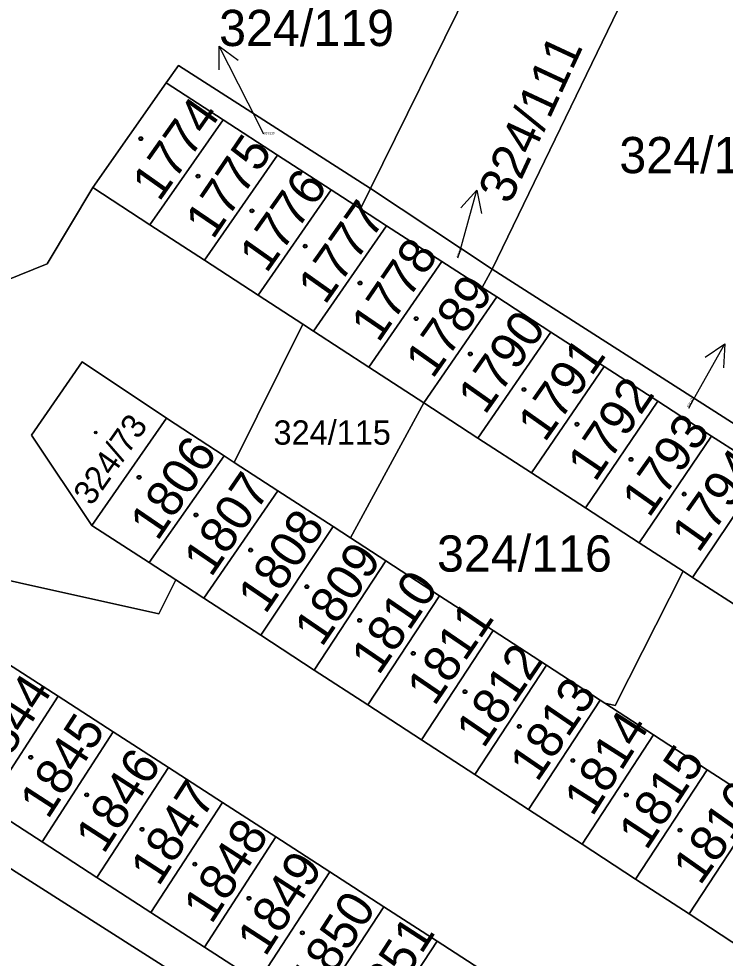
# Model space of a CAD drawing. Extents: x -598233 to -596890, y -1157848 to -1156431.
# Drawn here: x -597215.44 to -597182.25, y -1157620.12 to -1157576.01 of the extents above; entities that cross this region are included whole.
import ezdxf

# ---------------------------------------------------------------- set-up
doc = ezdxf.new("R2010")
doc.units = 0
for name, color, linetype in [('Level 1', 7, 'Continuous'), ('Level 4', 7, 'Continuous'), ('Level 5', 7, 'Continuous'), ('Level 57', 7, 'Continuous'), ('Level 60', 7, 'Continuous')]:
    doc.layers.add(name, color=color, linetype=linetype)

msp = doc.modelspace()

# ---------------------------------------------------------------- linework, layer by layer
at = {"layer": 'Level 1'}
for points in [[(-597198.92, -1157583.98), (-597189.61, -1157565.11)], [(-597193.21, -1157587.77), (-597184.82, -1157570.47)], [(-597208.52, -1157579.02), (-597207.94, -1157578.2), (-597198.92, -1157583.98)], [(-597211.97, -1157583.94), (-597208.52, -1157579.02)], [(-597208.52, -1157579.02), (-597205.84, -1157580.76)], [(-597205.84, -1157580.76), (-597209.28, -1157585.69)], [(-597205.84, -1157580.76), (-597203.28, -1157582.41)], [(-597206.72, -1157587.35), (-597203.28, -1157582.41)], [(-597203.28, -1157582.41), (-597200.77, -1157584.04)], [(-597228.65, -1157599.56), (-597223.33, -1157591.25), (-597214.11, -1157587.51), (-597211.97, -1157583.94)], [(-597209.28, -1157585.69), (-597211.97, -1157583.94)], [(-597198.92, -1157583.98), (-597199.39, -1157584.93)], [(-597198.92, -1157583.98), (-597193.21, -1157587.77)], [(-597204.2, -1157588.99), (-597200.77, -1157584.04)], [(-597200.77, -1157584.04), (-597199.39, -1157584.93)], [(-597199.39, -1157584.93), (-597198.16, -1157585.73)], [(-597209.28, -1157585.69), (-597206.72, -1157587.35)], [(-597198.16, -1157585.73), (-597201.59, -1157590.68)], [(-597198.16, -1157585.73), (-597195.57, -1157587.41)], [(-597204.2, -1157588.99), (-597206.72, -1157587.35)], [(-597198.99, -1157592.37), (-597195.57, -1157587.41)], [(-597195.57, -1157587.41), (-597193.67, -1157588.63)], [(-597193.21, -1157587.77), (-597193.67, -1157588.63)], [(-597193.21, -1157587.77), (-597181, -1157595.57)], [(-597193.67, -1157588.63), (-597192.99, -1157589.07)], [(-597202.09, -1157590.35), (-597204.2, -1157588.99)], [(-597192.99, -1157589.07), (-597196.41, -1157594.04)], [(-597192.99, -1157589.07), (-597190.45, -1157590.72)], [(-597202.09, -1157590.35), (-597205.32, -1157596.84)], [(-597201.59, -1157590.68), (-597202.09, -1157590.35)], [(-597201.59, -1157590.68), (-597198.99, -1157592.37)], [(-597193.87, -1157595.7), (-597190.45, -1157590.72)], [(-597190.45, -1157590.72), (-597187.94, -1157592.34)], [(-597212.01, -1157599.8), (-597214.85, -1157595.57), (-597212.47, -1157592.12), (-597208.51, -1157594.76)], [(-597198.99, -1157592.37), (-597196.41, -1157594.04)], [(-597187.94, -1157592.34), (-597191.35, -1157597.33)], [(-597187.94, -1157592.34), (-597185.42, -1157593.97)], [(-597199.86, -1157600.38), (-597196.41, -1157594.04)], [(-597196.41, -1157594.04), (-597193.87, -1157595.7)], [(-597185.42, -1157593.97), (-597188.82, -1157598.97)], [(-597185.42, -1157593.97), (-597182.89, -1157595.61)], [(-597208.51, -1157594.76), (-597212.01, -1157599.8)], [(-597205.79, -1157596.53), (-597208.51, -1157594.76)], [(-597191.35, -1157597.33), (-597193.87, -1157595.7)], [(-597186.29, -1157600.62), (-597182.89, -1157595.61)], [(-597182.89, -1157595.61), (-597181.48, -1157596.52)], [(-597205.79, -1157596.53), (-597209.31, -1157601.55)], [(-597205.32, -1157596.84), (-597205.79, -1157596.53)], [(-597203.27, -1157598.17), (-597205.32, -1157596.84)], [(-597180.4, -1157597.22), (-597183.79, -1157602.24)], [(-597191.35, -1157597.33), (-597188.82, -1157598.97)], [(-597206.75, -1157603.22), (-597203.27, -1157598.17)], [(-597200.68, -1157599.85), (-597203.27, -1157598.17)], [(-597188.82, -1157598.97), (-597186.29, -1157600.62)], [(-597144.73, -1157635.19), (-597124.59, -1157647.92), (-597112.62, -1157653.99), (-597115.75, -1157660.25), (-597114.28, -1157671.45), (-597118.54, -1157677.88), (-597228.54, -1157607.83), (-597232.29, -1157605.23), (-597228.65, -1157599.56)], [(-597208.07, -1157602.36), (-597208.87, -1157603.96), (-597228.65, -1157599.56)], [(-597212.01, -1157599.8), (-597209.31, -1157601.55)], [(-597200.68, -1157599.85), (-597204.07, -1157604.96)], [(-597199.86, -1157600.38), (-597200.68, -1157599.85)], [(-597198.2, -1157601.46), (-597199.86, -1157600.38)], [(-597184.23, -1157601.95), (-597186.29, -1157600.62)], [(-597209.31, -1157601.55), (-597208.07, -1157602.36)], [(-597201.56, -1157606.6), (-597198.2, -1157601.46)], [(-597195.67, -1157603.11), (-597198.2, -1157601.46)], [(-597187.91, -1157608.15), (-597187.42, -1157608.25), (-597184.23, -1157601.95)], [(-597183.79, -1157602.24), (-597184.23, -1157601.95)], [(-597208.07, -1157602.36), (-597206.75, -1157603.22)], [(-597183.79, -1157602.24), (-597181.21, -1157603.91)], [(-597206.75, -1157603.22), (-597204.07, -1157604.96)], [(-597195.67, -1157603.11), (-597199.04, -1157608.23)], [(-597193.15, -1157604.74), (-597195.67, -1157603.11)], [(-597193.15, -1157604.74), (-597196.53, -1157609.87)], [(-597190.65, -1157606.37), (-597193.15, -1157604.74)], [(-597204.07, -1157604.96), (-597201.56, -1157606.6)], [(-597216.19, -1157606.14), (-597213.59, -1157607.82)], [(-597194.01, -1157611.5), (-597190.65, -1157606.37)], [(-597188.13, -1157608.01), (-597190.65, -1157606.37)], [(-597201.56, -1157606.6), (-597199.04, -1157608.23)], [(-597213.59, -1157607.82), (-597216.94, -1157612.98)], [(-597213.59, -1157607.82), (-597211.01, -1157609.49)], [(-597199.04, -1157608.23), (-597196.53, -1157609.87)], [(-597188.13, -1157608.01), (-597191.5, -1157613.14)], [(-597187.91, -1157608.15), (-597188.13, -1157608.01)], [(-597185.62, -1157609.64), (-597187.91, -1157608.15)], [(-597214.35, -1157614.66), (-597211.01, -1157609.49)], [(-597211.01, -1157609.49), (-597208.41, -1157611.17)], [(-597196.53, -1157609.87), (-597194.01, -1157611.5)], [(-597185.62, -1157609.64), (-597188.98, -1157614.77)], [(-597183.1, -1157611.28), (-597185.62, -1157609.64)], [(-597211.78, -1157616.33), (-597208.41, -1157611.17)], [(-597208.41, -1157611.17), (-597205.87, -1157612.81)], [(-597186.47, -1157616.41), (-597183.1, -1157611.28)], [(-597180.58, -1157612.91), (-597183.1, -1157611.28)], [(-597194.01, -1157611.5), (-597191.5, -1157613.14)], [(-597214.35, -1157614.66), (-597216.94, -1157612.98)], [(-597205.87, -1157612.81), (-597209.24, -1157617.98)], [(-597205.87, -1157612.81), (-597203.36, -1157614.43)], [(-597183.95, -1157618.04), (-597180.58, -1157612.91)], [(-597191.5, -1157613.14), (-597188.98, -1157614.77)], [(-597206.72, -1157619.61), (-597203.36, -1157614.43)], [(-597203.36, -1157614.43), (-597200.83, -1157616.07)], [(-597211.78, -1157616.33), (-597214.35, -1157614.66)], [(-597188.98, -1157614.77), (-597186.47, -1157616.41)], [(-597200.83, -1157616.07), (-597204.2, -1157621.24)], [(-597200.83, -1157616.07), (-597198.29, -1157617.71)], [(-597209.24, -1157617.98), (-597211.78, -1157616.33)], [(-597186.47, -1157616.41), (-597183.95, -1157618.04)], [(-597206.72, -1157619.61), (-597209.24, -1157617.98)], [(-597198.29, -1157617.71), (-597201.67, -1157622.88)], [(-597198.29, -1157617.71), (-597195.79, -1157619.33)], [(-597183.95, -1157618.04), (-597181.44, -1157619.68)], [(-597204.2, -1157621.24), (-597206.72, -1157619.61)], [(-597195.79, -1157619.33), (-597199.18, -1157624.5)], [(-597195.79, -1157619.33), (-597193.21, -1157621)]]:
    msp.add_lwpolyline(points, dxfattribs=at)
at = {"layer": 'Level 5'}
for centre, radius in [((-597209.71, -1157581.64), 0.09), ((-597209.71, -1157581.64), 0.0521), ((-597207.02, -1157583.4), 0.09), ((-597207.02, -1157583.4), 0.0521), ((-597204.49, -1157585.03), 0.09), ((-597204.49, -1157585.03), 0.0521), ((-597201.99, -1157586.69), 0.09), ((-597201.99, -1157586.69), 0.0521), ((-597199.41, -1157588.42), 0.09), ((-597199.41, -1157588.42), 0.0521), ((-597196.77, -1157590.09), 0.09), ((-597196.77, -1157590.09), 0.0521), ((-597194.23, -1157591.75), 0.09), ((-597194.23, -1157591.75), 0.0521), ((-597191.71, -1157593.42), 0.09), ((-597191.71, -1157593.42), 0.0521), ((-597189.22, -1157595.05), 0.09), ((-597189.22, -1157595.05), 0.0521), ((-597211.83, -1157595.44), 0.0612), ((-597211.83, -1157595.44), 0.0354), ((-597186.68, -1157596.7), 0.09), ((-597186.68, -1157596.7), 0.0521), ((-597209.79, -1157597.54), 0.09), ((-597209.79, -1157597.54), 0.0521), ((-597184.18, -1157598.33), 0.09), ((-597184.18, -1157598.33), 0.0521), ((-597207.12, -1157599.31), 0.09), ((-597207.12, -1157599.31), 0.0521), ((-597204.55, -1157600.96), 0.09), ((-597204.55, -1157600.96), 0.0521), ((-597201.91, -1157602.68), 0.09), ((-597201.91, -1157602.68), 0.0521), ((-597199.43, -1157604.26), 0.09), ((-597199.43, -1157604.26), 0.0521), ((-597196.91, -1157605.81), 0.09), ((-597196.91, -1157605.81), 0.0521), ((-597194.48, -1157607.61), 0.09), ((-597194.48, -1157607.61), 0.0521), ((-597191.93, -1157609.24), 0.09), ((-597191.93, -1157609.24), 0.0521), ((-597214.88, -1157610.69), 0.09), ((-597214.88, -1157610.69), 0.0521), ((-597189.41, -1157610.84), 0.09), ((-597189.41, -1157610.84), 0.0521), ((-597212.25, -1157612.45), 0.09), ((-597212.25, -1157612.45), 0.0521), ((-597186.9, -1157612.46), 0.09), ((-597186.9, -1157612.46), 0.0521), ((-597209.65, -1157614.07), 0.09), ((-597209.65, -1157614.07), 0.0521), ((-597184.38, -1157614.11), 0.09), ((-597184.38, -1157614.11), 0.0521), ((-597207.17, -1157615.71), 0.09), ((-597207.17, -1157615.71), 0.0521), ((-597204.63, -1157617.31), 0.09), ((-597204.63, -1157617.31), 0.0521), ((-597202.12, -1157618.93), 0.09), ((-597202.12, -1157618.93), 0.0521)]:
    msp.add_circle(centre, radius, dxfattribs=at)
at = {"layer": 'Level 57'}
for p, q in [((-597204.673, -1157579.965), (-597206.03, -1157577.29)), ((-597203.93, -1157581.43), (-597204.673, -1157579.965)), ((-597194.729, -1157586.952), (-597193.921, -1157584.063)), ((-597194.81, -1157587.24), (-597194.729, -1157586.952)), ((-597183.745, -1157593.891), (-597182.273, -1157591.277)), ((-597183.97, -1157594.29), (-597183.745, -1157593.891))]:
    msp.add_line(p, q, dxfattribs=at)
for points in [[(-597206.024, -1157578.408), (-597206.03, -1157577.29), (-597205.132, -1157577.955)], [(-597194.672, -1157584.891), (-597193.921, -1157584.063), (-597193.709, -1157585.161)], [(-597183.199, -1157591.903), (-597182.273, -1157591.277), (-597182.328, -1157592.394)]]:
    msp.add_lwpolyline(points, dxfattribs=at)
at = {"layer": 'Level 60'}
for points in [[(-597207.94, -1157578.2), (-597208.52, -1157579.02), (-597211.97, -1157583.94), (-597214.11, -1157587.51), (-597223.33, -1157591.25), (-597228.65, -1157599.56), (-597234.25, -1157598.31), (-597227.4, -1157584.44), (-597226.39, -1157582.29), (-597222.52, -1157574.19), (-597220.91, -1157570.63), (-597219.84, -1157568.42), (-597217.55, -1157563.4), (-597212.54, -1157554.36), (-597208.4, -1157546.34), (-597208.14, -1157545.66), (-597207.64, -1157544.59), (-597189.61, -1157565.11), (-597198.92, -1157583.98)], [(-597193.21, -1157587.77), (-597198.92, -1157583.98), (-597189.61, -1157565.11), (-597184.82, -1157570.47)], [(-597181, -1157595.57), (-597193.21, -1157587.77), (-597184.82, -1157570.47), (-597174.68, -1157581.87)], [(-597208.52, -1157579.02), (-597207.94, -1157578.2), (-597198.92, -1157583.98), (-597199.39, -1157584.93), (-597200.77, -1157584.04), (-597203.28, -1157582.41), (-597205.84, -1157580.76)], [(-597208.52, -1157579.02), (-597205.84, -1157580.76), (-597209.28, -1157585.69), (-597211.97, -1157583.94)], [(-597205.84, -1157580.76), (-597203.28, -1157582.41), (-597206.72, -1157587.35), (-597209.28, -1157585.69)], [(-597203.28, -1157582.41), (-597200.77, -1157584.04), (-597204.2, -1157588.99), (-597206.72, -1157587.35)], [(-597223.33, -1157591.25), (-597214.11, -1157587.51), (-597211.97, -1157583.94), (-597209.28, -1157585.69), (-597206.72, -1157587.35), (-597204.2, -1157588.99), (-597202.09, -1157590.35), (-597205.32, -1157596.84), (-597205.79, -1157596.53), (-597208.51, -1157594.76), (-597212.47, -1157592.12), (-597214.85, -1157595.57), (-597212.01, -1157599.8), (-597209.31, -1157601.55), (-597208.07, -1157602.36), (-597208.87, -1157603.96), (-597228.65, -1157599.56)], [(-597195.57, -1157587.41), (-597198.16, -1157585.73), (-597199.39, -1157584.93), (-597198.92, -1157583.98), (-597193.21, -1157587.77), (-597193.67, -1157588.63)], [(-597198.16, -1157585.73), (-597201.59, -1157590.68), (-597202.09, -1157590.35), (-597204.2, -1157588.99), (-597200.77, -1157584.04), (-597199.39, -1157584.93)], [(-597198.16, -1157585.73), (-597195.57, -1157587.41), (-597198.99, -1157592.37), (-597201.59, -1157590.68)], [(-597192.99, -1157589.07), (-597196.41, -1157594.04), (-597198.99, -1157592.37), (-597195.57, -1157587.41), (-597193.67, -1157588.63)], [(-597182.89, -1157595.61), (-597185.42, -1157593.97), (-597187.94, -1157592.34), (-597190.45, -1157590.72), (-597192.99, -1157589.07), (-597193.67, -1157588.63), (-597193.21, -1157587.77), (-597181, -1157595.57), (-597181.48, -1157596.52)], [(-597192.99, -1157589.07), (-597190.45, -1157590.72), (-597193.87, -1157595.7), (-597196.41, -1157594.04)], [(-597200.68, -1157599.85), (-597203.27, -1157598.17), (-597205.32, -1157596.84), (-597202.09, -1157590.35), (-597201.59, -1157590.68), (-597198.99, -1157592.37), (-597196.41, -1157594.04), (-597199.86, -1157600.38)], [(-597190.45, -1157590.72), (-597187.94, -1157592.34), (-597191.35, -1157597.33), (-597193.87, -1157595.7)], [(-597208.51, -1157594.76), (-597212.01, -1157599.8), (-597214.85, -1157595.57), (-597212.47, -1157592.12)], [(-597187.94, -1157592.34), (-597185.42, -1157593.97), (-597188.82, -1157598.97), (-597191.35, -1157597.33)], [(-597195.67, -1157603.11), (-597198.2, -1157601.46), (-597199.86, -1157600.38), (-597196.41, -1157594.04), (-597193.87, -1157595.7), (-597191.35, -1157597.33), (-597188.82, -1157598.97), (-597186.29, -1157600.62), (-597184.23, -1157601.95), (-597187.42, -1157608.25), (-597187.91, -1157608.15), (-597188.13, -1157608.01), (-597190.65, -1157606.37), (-597193.15, -1157604.74)], [(-597185.42, -1157593.97), (-597182.89, -1157595.61), (-597186.29, -1157600.62), (-597188.82, -1157598.97)], [(-597212.01, -1157599.8), (-597208.51, -1157594.76), (-597205.79, -1157596.53), (-597209.31, -1157601.55)], [(-597180.4, -1157597.22), (-597183.79, -1157602.24), (-597184.23, -1157601.95), (-597186.29, -1157600.62), (-597182.89, -1157595.61), (-597181.48, -1157596.52)], [(-597209.31, -1157601.55), (-597205.79, -1157596.53), (-597205.32, -1157596.84), (-597203.27, -1157598.17), (-597206.75, -1157603.22), (-597208.07, -1157602.36)], [(-597180.4, -1157597.22), (-597177.83, -1157598.89), (-597181.21, -1157603.91), (-597183.79, -1157602.24)], [(-597203.27, -1157598.17), (-597200.68, -1157599.85), (-597204.07, -1157604.96), (-597206.75, -1157603.22)], [(-597204.07, -1157604.96), (-597200.68, -1157599.85), (-597199.86, -1157600.38), (-597198.2, -1157601.46), (-597201.56, -1157606.6)], [(-597198.2, -1157601.46), (-597195.67, -1157603.11), (-597199.04, -1157608.23), (-597201.56, -1157606.6)], [(-597199.04, -1157608.23), (-597195.67, -1157603.11), (-597193.15, -1157604.74), (-597196.53, -1157609.87)], [(-597193.15, -1157604.74), (-597190.65, -1157606.37), (-597194.01, -1157611.5), (-597196.53, -1157609.87)], [(-597216.94, -1157612.98), (-597219.55, -1157611.28), (-597216.19, -1157606.14), (-597213.59, -1157607.82)], [(-597190.65, -1157606.37), (-597188.13, -1157608.01), (-597191.5, -1157613.14), (-597194.01, -1157611.5)], [(-597214.35, -1157614.66), (-597216.94, -1157612.98), (-597213.59, -1157607.82), (-597211.01, -1157609.49)], [(-597191.5, -1157613.14), (-597188.13, -1157608.01), (-597187.91, -1157608.15), (-597185.62, -1157609.64), (-597188.98, -1157614.77)], [(-597211.78, -1157616.33), (-597214.35, -1157614.66), (-597211.01, -1157609.49), (-597208.41, -1157611.17)], [(-597185.62, -1157609.64), (-597183.1, -1157611.28), (-597186.47, -1157616.41), (-597188.98, -1157614.77)], [(-597209.24, -1157617.98), (-597211.78, -1157616.33), (-597208.41, -1157611.17), (-597205.87, -1157612.81)], [(-597186.47, -1157616.41), (-597183.1, -1157611.28), (-597180.58, -1157612.91), (-597183.95, -1157618.04)], [(-597206.72, -1157619.61), (-597209.24, -1157617.98), (-597205.87, -1157612.81), (-597203.36, -1157614.43)], [(-597180.58, -1157612.91), (-597178.05, -1157614.56), (-597181.44, -1157619.68), (-597183.95, -1157618.04)], [(-597204.2, -1157621.24), (-597206.72, -1157619.61), (-597203.36, -1157614.43), (-597200.83, -1157616.07)], [(-597201.67, -1157622.88), (-597204.2, -1157621.24), (-597200.83, -1157616.07), (-597198.29, -1157617.71)], [(-597199.18, -1157624.5), (-597201.67, -1157622.88), (-597198.29, -1157617.71), (-597195.79, -1157619.33)], [(-597196.61, -1157626.17), (-597199.18, -1157624.5), (-597195.79, -1157619.33), (-597193.21, -1157621)]]:
    msp.add_lwpolyline(points, close=True, dxfattribs=at)
for points in [[(-597115.94, -1157685.24), (-597179.87, -1157644.26), (-597206.27, -1157628.35), (-597223.03, -1157616.87), (-597239.94, -1157604.31), (-597245.81, -1157601.01), (-597245.52, -1157600.94), (-597244.68, -1157600.76), (-597243.36, -1157600.43), (-597234.25, -1157598.31), (-597228.65, -1157599.56), (-597232.29, -1157605.23), (-597228.54, -1157607.83), (-597118.54, -1157677.88)], [(-597118.54, -1157677.88), (-597228.54, -1157607.83), (-597232.29, -1157605.23), (-597228.65, -1157599.56), (-597208.87, -1157603.96), (-597208.07, -1157602.36), (-597206.75, -1157603.22), (-597204.07, -1157604.96), (-597201.56, -1157606.6), (-597199.04, -1157608.23), (-597196.53, -1157609.87), (-597194.01, -1157611.5), (-597191.5, -1157613.14), (-597188.98, -1157614.77), (-597186.47, -1157616.41), (-597183.95, -1157618.04), (-597181.44, -1157619.68)], [(-597193.21, -1157621), (-597195.79, -1157619.33), (-597198.29, -1157617.71), (-597200.83, -1157616.07), (-597203.36, -1157614.43), (-597205.87, -1157612.81), (-597208.41, -1157611.17), (-597211.01, -1157609.49), (-597213.59, -1157607.82), (-597216.19, -1157606.14), (-597218.73, -1157604.49), (-597221.29, -1157602.84), (-597223.96, -1157601.11), (-597227.31, -1157606.25), (-597224.63, -1157607.99), (-597222.07, -1157609.65), (-597219.55, -1157611.28), (-597216.94, -1157612.98), (-597214.35, -1157614.66), (-597211.78, -1157616.33), (-597209.24, -1157617.98), (-597206.72, -1157619.61), (-597204.2, -1157621.24)], [(-597180.58, -1157612.91), (-597183.1, -1157611.28), (-597185.62, -1157609.64), (-597187.91, -1157608.15), (-597187.42, -1157608.25), (-597184.23, -1157601.95), (-597183.79, -1157602.24), (-597181.21, -1157603.91)]]:
    msp.add_lwpolyline(points, dxfattribs=at)

# ---------------------------------------------------------------- texts
at = {"layer": 'Level 4'}
for s, height, rotation, p in [('1774', 1.7, 54.7505, (-597208.848, -1157584.646)), ('1775', 1.7, 55.8422, (-597206.321, -1157586.421)), ('1776', 1.7, 54.7505, (-597203.808, -1157588.006)), ('1777', 1.7, 54.7505, (-597201.057, -1157589.487)), ('1778', 1.7, 55.6601, (-597198.542, -1157591.268)), ('324/111', 0.1, 65.0466, (-597194.81, -1157587.24)), ('1789', 1.7, 54.7505, (-597196.002, -1157592.964)), ('1790', 1.7, 54.7505, (-597193.542, -1157594.654)), ('1791', 1.7, 54.7505, (-597190.731, -1157595.944)), ('1792', 1.7, 55.7989, (-597188.365, -1157597.809)), ('324/112', 0.1, 65.2037, (-597183.97, -1157594.29)), ('324/73', 1.14, 54.9137, (-597212.024, -1157598.924)), ('1793', 1.7, 54.7505, (-597185.833, -1157599.488)), ('1806', 1.7, 55.6601, (-597208.929, -1157600.581)), ('1794', 1.7, 54.7505, (-597183.508, -1157601.145)), ('1807', 1.7, 55.6601, (-597206.409, -1157602.282)), ('1808', 1.7, 55.6601, (-597203.859, -1157604.016)), ('1809', 1.7, 55.6601, (-597201.209, -1157605.561)), ('1810', 1.7, 55.6601, (-597198.536, -1157606.888)), ('1811', 1.7, 55.6601, (-597195.919, -1157608.335)), ('1812', 1.7, 55.6601, (-597193.609, -1157610.322)), ('1844', 1.7, 57.1069, (-597216.573, -1157611.79)), ('1813', 1.7, 55.6601, (-597191.086, -1157611.902)), ('1845', 1.7, 57.1069, (-597214.075, -1157613.645)), ('1814', 1.7, 57.5913, (-597188.494, -1157613.521)), ('1846', 1.7, 57.1069, (-597211.453, -1157615.28)), ('1815', 1.7, 56.5025, (-597185.954, -1157615.107)), ('1847', 1.7, 57.1069, (-597208.873, -1157616.801)), ('1816', 1.7, 54.7505, (-597183.435, -1157616.753)), ('1848', 1.7, 57.1069, (-597206.392, -1157618.575)), ('1849', 1.7, 57.1069, (-597203.863, -1157620.1)), ('1850', 1.7, 57.1069, (-597201.358, -1157621.985)), ('1851', 1.7, 57.1069, (-597198.588, -1157623.167))]:
    msp.add_text(s, height=height, rotation=rotation, dxfattribs=at).set_placement(p)
for s, height, p in [('324/119', 0.1, (-597203.93, -1157581.43)), ('324/107', 1.7, (-597187.229, -1157583.26)), ('324/115', 1.14, (-597203.473, -1157596.01)), ('324/116', 1.7, (-597195.793, -1157601.97))]:
    msp.add_text(s, height=height, dxfattribs=at).set_placement(p)
at = {"layer": 'Level 57'}
msp.add_text('324/119', height=1.7, dxfattribs=at).set_placement((-597206.03, -1157577.29))
msp.add_text('324/111', height=1.7, rotation=65.0466, dxfattribs=at).set_placement((-597192.38, -1157584.78))

doc.saveas('drawing.dxf')
